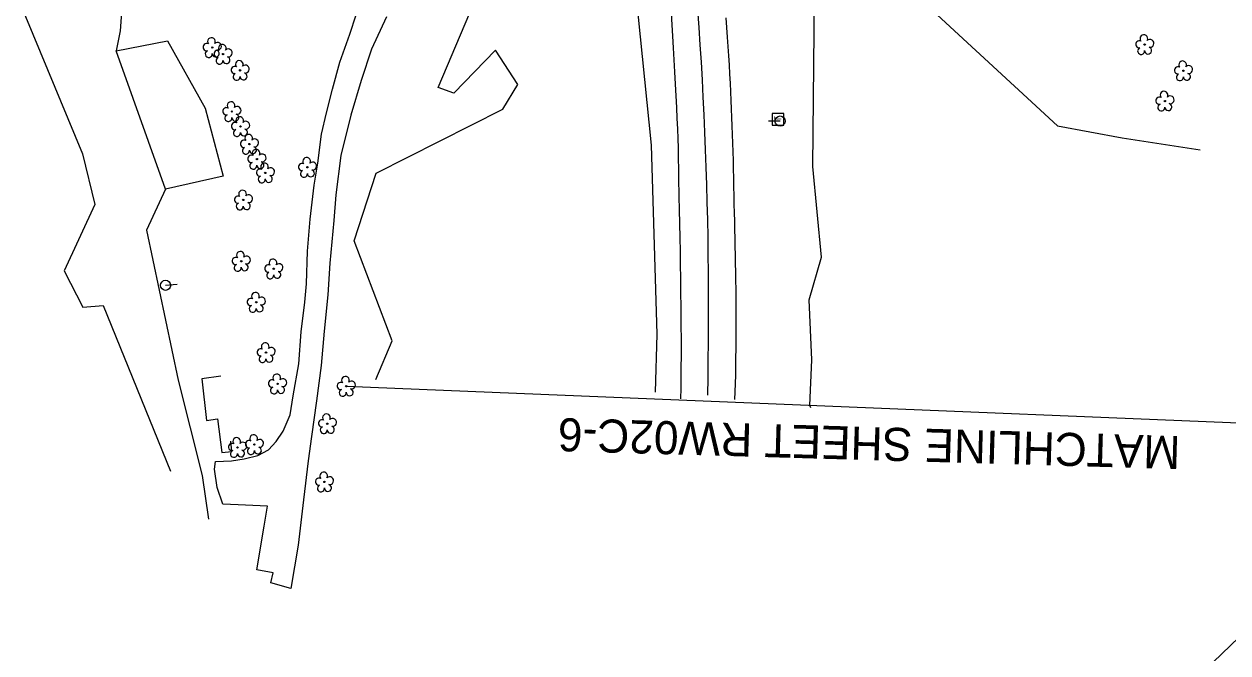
# Model space of a CAD drawing. Extents: x 471894 to 476235, y 503501 to 507878.
# Drawn here: x 474193 to 474775, y 504296 to 504600 of the extents above; entities that cross this region are included whole.
import ezdxf

# ---------------------------------------------------------------- set-up
doc = ezdxf.new("R2010")
doc.units = 0
for name, color, linetype in [('CTL Sheet Border CELL', 7, 'Continuous'), ('Exist Horizontal Alignment', 7, 'Continuous'), ('Exist Other Culture Area Outline', 7, 'Continuous'), ('Exist Roads EOP', 7, 'Continuous'), ('Exist Roads Soil', 7, 'Continuous'), ('Exist Utilities Power Pole CELL', 7, 'Continuous'), ('Exist Utilities Telephone Pedestal CELL', 7, 'Continuous'), ('Exist Vegetation Hedge Row', 7, 'Continuous'), ('Exist Vegetation Tree CELL', 7, 'Continuous'), ('Exist Vegetation Woods Line', 7, 'Continuous'), ('Matchline', 7, 'Continuous'), ('Matchline Text', 7, 'Continuous')]:
    doc.layers.add(name, color=color, linetype=linetype)

msp = doc.modelspace()

# ---------------------------------------------------------------- linework, layer by layer
at = {"layer": 'CTL Sheet Border CELL'}
msp.add_lwpolyline([(471959.97, 506199.96), (474263.4, 503806.21), (475939.01, 505418.6), (473635.58, 507812.35)], close=True, dxfattribs=at)
at = {"layer": 'Exist Horizontal Alignment'}
msp.add_arc((472536.78, 504463.34), 1987.17, 358.7675, 14.39186, dxfattribs=at)
at = {"layer": 'Exist Other Culture Area Outline'}
msp.add_lwpolyline([(474288.28, 504429.69), (474279.05, 504428.36), (474281.36, 504408.23), (474286.6, 504409.15), (474288.69, 504392.76), (474293.65, 504393.31), (474293.1, 504398.33)], dxfattribs=at)
at = {"layer": 'Exist Roads EOP'}
for points in [[(474510.55, 504418.72), (474510.64, 504423.83), (474510.71, 504429.42), (474510.75, 504435.26), (474510.77, 504438.29), (474510.78, 504441.5), (474510.77, 504445), (474510.76, 504448.8), (474510.73, 504452.9), (474510.69, 504457.05), (474510.65, 504461.02), (474510.61, 504464.82), (474510.56, 504468.44), (474510.52, 504471.94), (474510.48, 504475.34), (474510.45, 504478.67), (474510.42, 504481.91), (474510.39, 504485.13), (474510.35, 504488.39), (474510.31, 504491.69), (474510.25, 504495.03), (474510.18, 504498.39), (474510.11, 504501.76), (474510.03, 504505.13), (474509.95, 504508.5), (474509.86, 504511.82), (474509.79, 504515.03), (474509.72, 504518.12), (474509.61, 504524), (474509.51, 504529.66), (474509.43, 504535.1), (474509.33, 504540.04), (474509.19, 504544.53), (474509.01, 504549.23), (474508.79, 504554.25), (474508.54, 504559.58), (474508.25, 504565.19), (474507.95, 504570.95), (474507.64, 504576.82), (474507.33, 504582.71), (474507.01, 504588.54), (474506.67, 504594.15), (474506.3, 504599.55), (474505.93, 504605.16)], [(474532.28, 504603.03), (474532.63, 504598.33), (474532.97, 504593.71), (474533.28, 504589.16), (474533.57, 504584.66), (474533.84, 504580.2), (474534.08, 504575.79), (474534.3, 504571.44), (474534.5, 504567.18), (474534.69, 504563), (474534.86, 504558.9), (474535.03, 504554.83), (474535.19, 504550.72), (474535.34, 504546.59), (474535.5, 504542.41), (474535.64, 504538.21), (474535.76, 504534), (474535.87, 504529.78), (474535.95, 504525.54), (474536.02, 504521.31), (474536.11, 504517.09), (474536.2, 504512.9), (474536.31, 504508.72), (474536.42, 504504.58), (474536.51, 504500.47), (474536.6, 504496.39), (474536.68, 504492.36), (474536.75, 504488.32), (474536.83, 504484.23), (474536.91, 504480.09), (474536.99, 504475.9), (474537.06, 504471.72), (474537.11, 504467.58), (474537.13, 504463.49), (474537.14, 504459.46), (474537.12, 504455.42), (474537.11, 504451.31), (474537.08, 504447.13), (474537.05, 504442.89), (474537, 504438.64), (474536.94, 504434.43), (474536.86, 504430.27), (474536.75, 504426.15), (474536.64, 504422.05), (474536.52, 504418.37)]]:
    msp.add_lwpolyline(points, dxfattribs=at)
at = {"layer": 'Exist Roads Soil'}
msp.add_lwpolyline([(474368.33, 504603.4), (474361.1, 504587.83), (474356.14, 504572.6), (474351.13, 504555.87), (474346.21, 504536.46), (474343.81, 504517.37), (474342.82, 504504.9), (474340.98, 504484.39), (474339.97, 504469.03), (474338.24, 504451.51), (474336.67, 504434.79), (474334.45, 504417.79), (474331.99, 504400.48), (474330.54, 504388.83), (474328.19, 504369.97), (474325.56, 504347.93), (474322.02, 504327.01), (474312.44, 504329.74), (474313.58, 504334.59), (474305.58, 504336.12), (474309.15, 504357.23), (474310.84, 504366.79), (474296.71, 504367.46), (474289.31, 504367.76), (474286.56, 504375.81), (474285.17, 504384.8), (474285.62, 504388.51), (474293.35, 504388.81), (474299.53, 504389.75), (474306.15, 504391.41), (474311.32, 504394.14), (474314.94, 504398.12), (474318.41, 504403.11), (474321.73, 504410.94), (474323.29, 504420.23), (474325.97, 504435.65), (474327.13, 504451.09), (474328.8, 504465.46), (474329.6, 504474.32), (474330.09, 504490.11), (474331.47, 504505.58), (474333.34, 504522.1), (474335.09, 504532.63), (474336.96, 504546.73), (474339.39, 504556.99), (474342.2, 504568.41), (474345.74, 504581.56), (474350.55, 504595.06), (474353.61, 504604.35)], dxfattribs=at)
at = {"layer": 'Exist Utilities Power Pole CELL'}
for p, q in [((474558.45, 504553.07), (474552.83, 504553.07)), ((474558.45, 504553.07), (474558.45, 504553.07)), ((474261.58, 504473.63), (474267.17, 504474.2)), ((474261.58, 504473.63), (474261.58, 504473.63))]:
    msp.add_line(p, q, dxfattribs=at)
for centre in [(474558.45, 504553.07), (474261.58, 504473.63)]:
    msp.add_circle(centre, 2.45, dxfattribs=at)
at = {"layer": 'Exist Utilities Telephone Pedestal CELL'}
msp.add_line((474557.39, 504553.79), (474557.39, 504553.79), dxfattribs=at)
msp.add_lwpolyline([(474560.21, 504551.06), (474560.21, 504556.66), (474554.62, 504556.66), (474554.62, 504551.06), (474560.21, 504551.06)], dxfattribs=at)
at = {"layer": 'Exist Vegetation Hedge Row'}
for points in [[(474139.09, 504552.19), (474151.55, 504629.91), (474164.24, 504664.12), (474188.29, 504706.88), (474198.29, 504718.2), (474209.11, 504724.87), (474227.92, 504725.12), (474234.92, 504714.69), (474215.17, 504701.05), (474199.72, 504687.62), (474221, 504644.93), (474233.14, 504642.04), (474241.52, 504623.67), (474239.57, 504596.64), (474237.63, 504586.96)], [(474261.56, 504520.14), (474252.4, 504500.24), (474267.64, 504427.72), (474279.27, 504381.67), (474282.33, 504360.53)]]:
    msp.add_lwpolyline(points, dxfattribs=at)
at = {"layer": 'Exist Vegetation Tree CELL'}
for p, q in [((474734.62, 504590.07), (474734.62, 504590.07)), ((474284.1, 504588.64), (474284.1, 504588.64)), ((474289.34, 504585.43), (474289.34, 504585.43)), ((474297.57, 504577.59), (474297.57, 504577.59)), ((474753.35, 504577.38), (474753.35, 504577.38)), ((474744.38, 504562.74), (474744.38, 504562.74)), ((474293.57, 504557.68), (474293.57, 504557.68)), ((474297.76, 504550.45), (474297.76, 504550.45)), ((474302.1, 504541.91), (474302.1, 504541.91)), ((474305.67, 504534.65), (474305.67, 504534.65)), ((474309.75, 504527.99), (474309.75, 504527.99)), ((474330.09, 504530.7), (474330.09, 504530.7)), ((474299.13, 504514.9), (474299.13, 504514.9)), ((474298.1, 504485.28), (474298.1, 504485.28)), ((474313.84, 504481.62), (474313.84, 504481.62)), ((474305.37, 504465.42), (474305.37, 504465.42)), ((474310.09, 504441.1), (474310.09, 504441.1)), ((474315.66, 504425.99), (474315.66, 504425.99)), ((474348.85, 504424.83), (474348.85, 504424.83)), ((474339.7, 504406.73), (474339.7, 504406.73)), ((474296.32, 504395.26), (474296.32, 504395.26)), ((474304.49, 504396.67), (474304.49, 504396.67)), ((474338.32, 504378.57), (474338.32, 504378.57))]:
    msp.add_line(p, q, dxfattribs=at)
for centre in [(474734.62, 504590.07), (474284.1, 504588.64), (474289.34, 504585.43), (474297.57, 504577.59), (474753.35, 504577.38), (474744.38, 504562.74), (474293.57, 504557.68), (474297.76, 504550.45), (474302.1, 504541.91), (474305.67, 504534.65), (474309.75, 504527.99), (474330.09, 504530.7), (474299.13, 504514.9), (474298.1, 504485.28), (474313.84, 504481.62), (474305.37, 504465.42), (474310.09, 504441.1), (474315.66, 504425.99), (474348.85, 504424.83), (474339.7, 504406.73), (474296.32, 504395.26), (474304.49, 504396.67), (474338.32, 504378.57)]:
    msp.add_circle(centre, 0.326, dxfattribs=at)
for centre, radius, start, end in [((474281.5, 504588.8), 1.73, 62.66361, 279.3457), ((474283.72, 504591.52), 1.86, 330.16508, 219.71335), ((474286.65, 504589.23), 1.9, 257.1011, 134.19993), ((474288.95, 504588.3), 1.86, 330.16508, 219.71335), ((474732.02, 504590.22), 1.73, 62.66361, 279.3457), ((474734.24, 504592.94), 1.86, 330.16508, 219.71335), ((474737.17, 504590.65), 1.9, 257.1011, 134.19993), ((474282.4, 504585.52), 1.69, 111.56708, 6.23104), ((474285.78, 504585.74), 1.7, 181.28216, 74.55999), ((474286.73, 504585.58), 1.73, 62.66361, 279.3457), ((474291.89, 504586.02), 1.9, 257.1011, 134.19993), ((474732.92, 504586.94), 1.69, 111.56708, 6.23104), ((474736.3, 504587.17), 1.7, 181.28216, 74.55999), ((474287.64, 504582.31), 1.69, 111.56708, 6.23104), ((474291.01, 504582.53), 1.7, 181.28216, 74.55999), ((474294.97, 504577.74), 1.73, 62.66361, 279.3457), ((474297.19, 504580.46), 1.86, 330.16508, 219.71335), ((474300.12, 504578.18), 1.9, 257.1011, 134.19993), ((474750.74, 504577.54), 1.73, 62.66361, 279.3457), ((474752.96, 504580.26), 1.86, 330.16508, 219.71335), ((474755.89, 504577.97), 1.9, 257.1011, 134.19993), ((474295.87, 504574.47), 1.69, 111.56708, 6.23104), ((474299.24, 504574.69), 1.7, 181.28216, 74.55999), ((474751.64, 504574.26), 1.69, 111.56708, 6.23104), ((474755.02, 504574.48), 1.7, 181.28216, 74.55999), ((474743.99, 504565.62), 1.86, 330.16508, 219.71335), ((474293.19, 504560.55), 1.86, 330.16508, 219.71335), ((474741.77, 504562.9), 1.73, 62.66361, 279.3457), ((474742.67, 504559.62), 1.69, 111.56708, 6.23104), ((474746.05, 504559.84), 1.7, 181.28216, 74.55999), ((474746.93, 504563.33), 1.9, 257.1011, 134.19993), ((474290.97, 504557.83), 1.73, 62.66361, 279.3457), ((474291.87, 504554.55), 1.69, 111.56708, 6.23104), ((474295.25, 504554.78), 1.7, 181.28216, 74.55999), ((474296.12, 504558.26), 1.9, 257.1011, 134.19993), ((474297.38, 504553.32), 1.86, 330.16508, 219.71335), ((474295.15, 504550.6), 1.73, 62.66361, 279.3457), ((474300.31, 504551.04), 1.9, 257.1011, 134.19993), ((474296.06, 504547.33), 1.69, 111.56708, 6.23104), ((474299.43, 504547.55), 1.7, 181.28216, 74.55999), ((474299.49, 504542.06), 1.73, 62.66361, 279.3457), ((474301.71, 504544.78), 1.86, 330.16508, 219.71335), ((474304.64, 504542.5), 1.9, 257.1011, 134.19993), ((474300.39, 504538.79), 1.69, 111.56708, 6.23104), ((474303.77, 504539.01), 1.7, 181.28216, 74.55999), ((474305.29, 504537.52), 1.86, 330.16508, 219.71335), ((474303.07, 504534.8), 1.73, 62.66361, 279.3457), ((474303.97, 504531.53), 1.69, 111.56708, 6.23104), ((474307.35, 504531.75), 1.7, 181.28216, 74.55999), ((474308.22, 504535.24), 1.9, 257.1011, 134.19993), ((474309.37, 504530.86), 1.86, 330.16508, 219.71335), ((474327.49, 504530.85), 1.73, 62.66361, 279.3457), ((474329.71, 504533.57), 1.86, 330.16508, 219.71335), ((474332.64, 504531.28), 1.9, 257.1011, 134.19993), ((474307.15, 504528.14), 1.73, 62.66361, 279.3457), ((474308.05, 504524.86), 1.69, 111.56708, 6.23104), ((474311.42, 504525.09), 1.7, 181.28216, 74.55999), ((474312.3, 504528.57), 1.9, 257.1011, 134.19993), ((474328.39, 504527.57), 1.69, 111.56708, 6.23104), ((474331.77, 504527.8), 1.7, 181.28216, 74.55999), ((474296.52, 504515.05), 1.73, 62.66361, 279.3457), ((474298.75, 504517.77), 1.86, 330.16508, 219.71335), ((474301.68, 504515.49), 1.9, 257.1011, 134.19993), ((474297.43, 504511.78), 1.69, 111.56708, 6.23104), ((474300.8, 504512), 1.7, 181.28216, 74.55999), ((474295.5, 504485.43), 1.73, 62.66361, 279.3457), ((474297.72, 504488.15), 1.86, 330.16508, 219.71335), ((474300.65, 504485.87), 1.9, 257.1011, 134.19993), ((474313.45, 504484.5), 1.86, 330.16508, 219.71335), ((474296.4, 504482.16), 1.69, 111.56708, 6.23104), ((474299.77, 504482.38), 1.7, 181.28216, 74.55999), ((474311.23, 504481.78), 1.73, 62.66361, 279.3457), ((474312.13, 504478.5), 1.69, 111.56708, 6.23104), ((474315.51, 504478.72), 1.7, 181.28216, 74.55999), ((474316.39, 504482.21), 1.9, 257.1011, 134.19993), ((474304.98, 504468.3), 1.86, 330.16508, 219.71335), ((474307.92, 504466.01), 1.9, 257.1011, 134.19993), ((474302.76, 504465.58), 1.73, 62.66361, 279.3457), ((474303.67, 504462.3), 1.69, 111.56708, 6.23104), ((474307.04, 504462.52), 1.7, 181.28216, 74.55999), ((474309.71, 504443.97), 1.86, 330.16508, 219.71335), ((474307.49, 504441.25), 1.73, 62.66361, 279.3457), ((474308.39, 504437.98), 1.69, 111.56708, 6.23104), ((474311.77, 504438.2), 1.7, 181.28216, 74.55999), ((474312.64, 504441.69), 1.9, 257.1011, 134.19993), ((474313.06, 504426.15), 1.73, 62.66361, 279.3457), ((474315.28, 504428.87), 1.86, 330.16508, 219.71335), ((474318.21, 504426.58), 1.9, 257.1011, 134.19993), ((474348.46, 504427.7), 1.86, 330.16508, 219.71335), ((474351.39, 504425.42), 1.9, 257.1011, 134.19993), ((474313.96, 504422.87), 1.69, 111.56708, 6.23104), ((474317.33, 504423.09), 1.7, 181.28216, 74.55999), ((474346.24, 504424.98), 1.73, 62.66361, 279.3457), ((474347.14, 504421.71), 1.69, 111.56708, 6.23104), ((474350.52, 504421.93), 1.7, 181.28216, 74.55999), ((474339.32, 504409.61), 1.86, 330.16508, 219.71335), ((474337.1, 504406.89), 1.73, 62.66361, 279.3457), ((474338, 504403.61), 1.69, 111.56708, 6.23104), ((474341.38, 504403.83), 1.7, 181.28216, 74.55999), ((474342.25, 504407.32), 1.9, 257.1011, 134.19993), ((474295.94, 504398.13), 1.86, 330.16508, 219.71335), ((474301.89, 504396.82), 1.73, 62.66361, 279.3457), ((474304.11, 504399.54), 1.86, 330.16508, 219.71335), ((474307.04, 504397.26), 1.9, 257.1011, 134.19993), ((474293.71, 504395.41), 1.73, 62.66361, 279.3457), ((474294.62, 504392.14), 1.69, 111.56708, 6.23104), ((474297.99, 504392.36), 1.7, 181.28216, 74.55999), ((474298.87, 504395.85), 1.9, 257.1011, 134.19993), ((474302.79, 504393.55), 1.69, 111.56708, 6.23104), ((474306.16, 504393.77), 1.7, 181.28216, 74.55999), ((474337.94, 504381.44), 1.86, 330.16508, 219.71335), ((474340.87, 504379.16), 1.9, 257.1011, 134.19993), ((474335.72, 504378.72), 1.73, 62.66361, 279.3457), ((474336.62, 504375.45), 1.69, 111.56708, 6.23104), ((474340, 504375.67), 1.7, 181.28216, 74.55999)]:
    msp.add_arc(centre, radius, start, end, dxfattribs=at)
at = {"layer": 'Exist Vegetation Woods Line'}
for points in [[(474573.25, 504414.35), (474572.77, 504415.48), (474573.79, 504437.62), (474572.49, 504466.63), (474578.42, 504487.31), (474574.29, 504531.07), (474575.09, 504612.99), (474560.94, 504648.27), (474563.82, 504670.61), (474581.92, 504660.54), (474632.35, 504606.43), (474692.54, 504550.79), (474723.72, 504545), (474761.48, 504539.14)], [(474139.09, 504552.19), (474155.17, 504560.15), (474156.57, 504605.34), (474167.19, 504647.42), (474176.84, 504644.56), (474221.5, 504537.29), (474227.36, 504512.7), (474212.61, 504480.68), (474221.58, 504463.05), (474231.43, 504463.83), (474264.02, 504383.76)], [(474363.17, 504428.14), (474370.99, 504446.82), (474352.61, 504495.07), (474363.26, 504527.87), (474424.56, 504558.83), (474431.82, 504570.68), (474421.04, 504587.28), (474400.87, 504566.59), (474393.26, 504569.34), (474419.43, 504631.05), (474460.12, 504622.89), (474489.82, 504604.99), (474496.17, 504541.35), (474498.87, 504449.99), (474498.04, 504421.91)], [(474237.63, 504586.96), (474262.49, 504591.85), (474280.74, 504559.3), (474289.33, 504526.38), (474261.56, 504520.14)], [(474261.56, 504520.14), (474237.63, 504586.96)]]:
    msp.add_lwpolyline(points, dxfattribs=at)
at = {"layer": 'Matchline'}
msp.add_line((474348.85, 504424.83), (474832.78, 504404.9), dxfattribs=at)

# ---------------------------------------------------------------- texts
at = {"layer": 'Exist Utilities Telephone Pedestal CELL'}
msp.add_text('T', height=3.42, rotation=90, dxfattribs=at).set_placement((474559.1, 504552.66))
at = {"layer": 'Matchline Text'}
msp.add_text('MATCHLINE SHEET RW02C-6', height=16, rotation=178.32958, dxfattribs=at).set_placement((474752.05, 504400.73))

doc.saveas('drawing.dxf')
